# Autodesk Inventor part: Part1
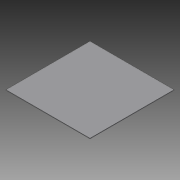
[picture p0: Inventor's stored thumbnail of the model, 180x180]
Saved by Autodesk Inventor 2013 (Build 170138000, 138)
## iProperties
Created: 2013-06
Part Number: Part1
Material: Generic
Document SubType Name: Modeling
Designer: jpfenske
Density: 1 g/cm^3
Author: jpfenske
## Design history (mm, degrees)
sketch "Sketch1"
  geometry: L1 (457.2, -457.2)-(-457.2, -457.2); L2 (-457.2, -457.2)-(-457.2, 457.2); L3 (-457.2, 457.2)-(457.2, 457.2); L4 (457.2, 457.2)-(457.2, -457.2); L5 (457.2, -457.2)-(-457.2, 457.2); L6 (-457.2, -457.2)-(457.2, 457.2); 1 further point
  constraints: 12 end point, 2 midpoint, 2 parallel, 1 horizontal, 1 perpendicular
  dimensions: "d2" = 914.4 distance of L2.end L3.end; "d4" = 914.4 distance of L1.end L2.end
extrude "Extrusion1" new body sketch "Sketch1" distance "d0" = 6.35; taper "d1" = 0 deg
body "Solid1"
